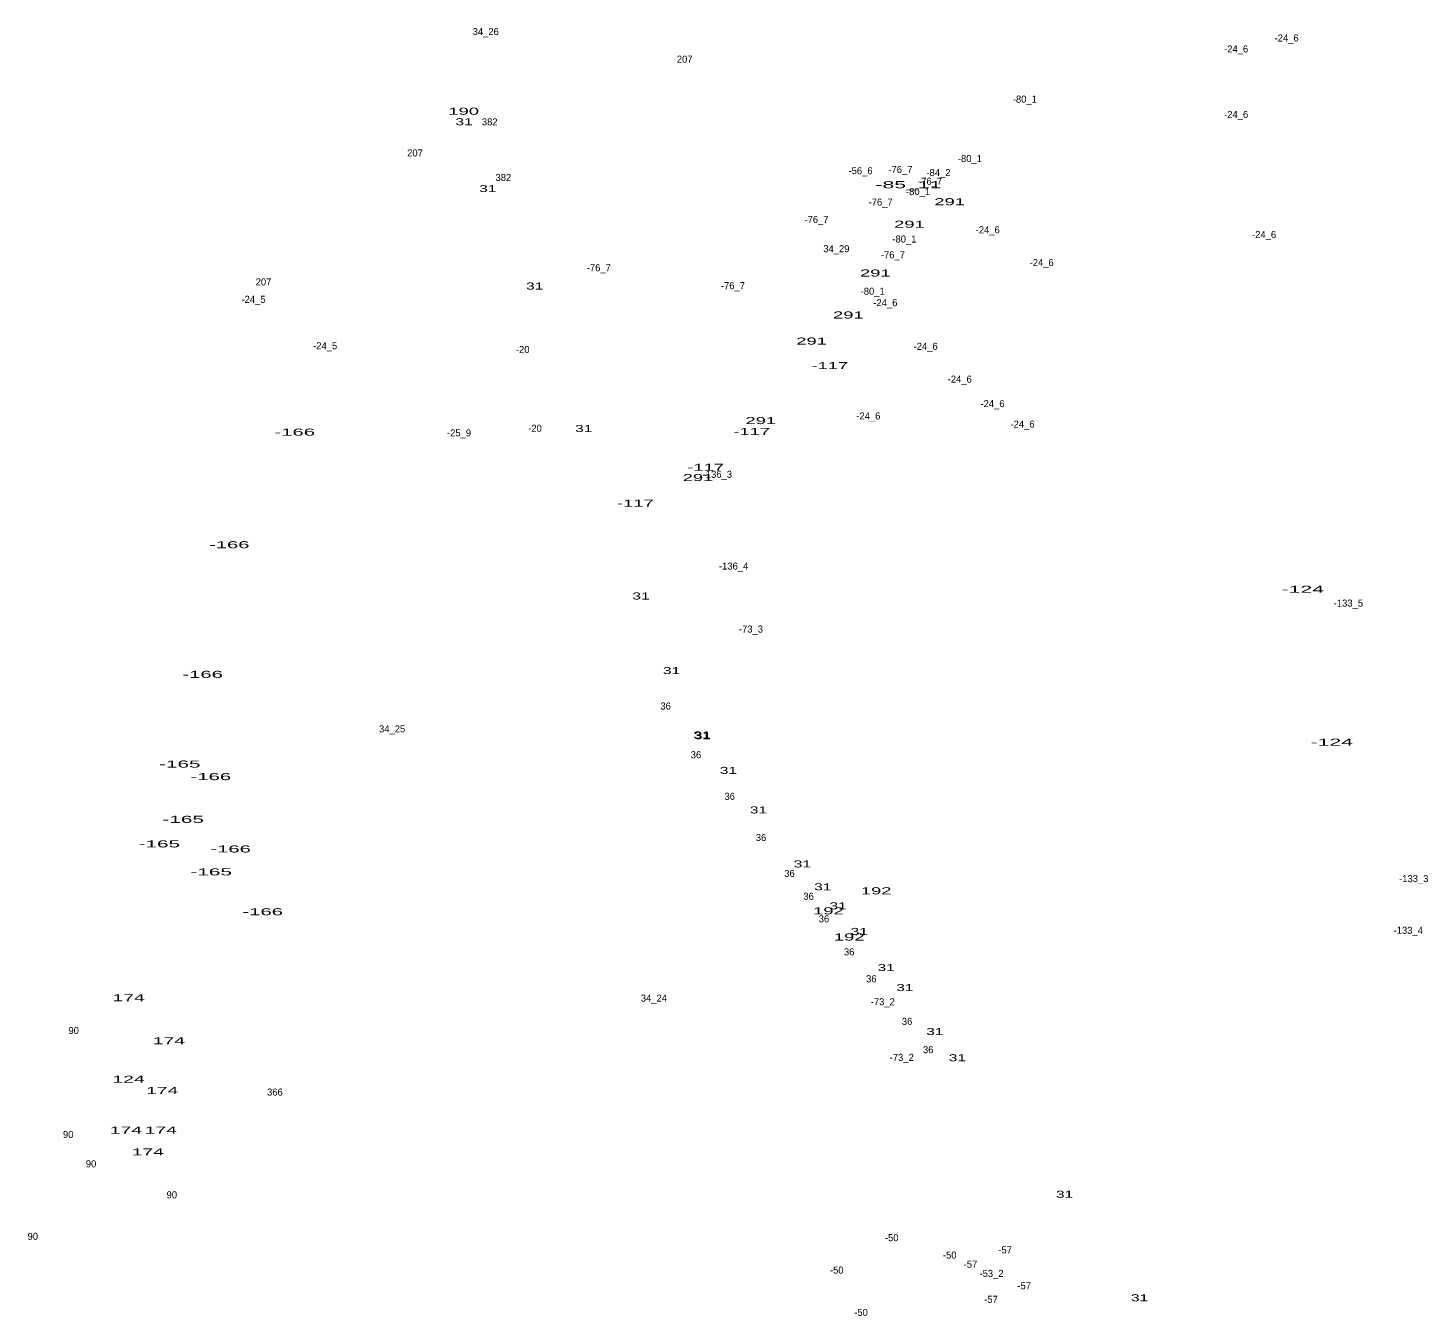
# Model space of a CAD drawing. Extents: x -662499 to -659675, y -1001682 to -998165.
# Drawn here: x -660470 to -659675, y -999900 to -999168 of the extents above; entities that cross this region are included whole.
import ezdxf
from ezdxf.enums import TextEntityAlignment as Align

# ---------------------------------------------------------------- set-up
doc = ezdxf.new("R2010")
doc.units = 0
doc.header["$LTSCALE"] = 1.6
doc.layers.add('24', color=7, linetype='Continuous')

msp = doc.modelspace()

# ---------------------------------------------------------------- texts
at = {"layer": '24'}
for s, p in [('34_26', (-660210.064, -999172.46)), ('-24_6', (-659754.992, -999176.09)), ('207', (-660097.017, -999188.1)), ('-24_6', (-659783.682, -999182.3)), ('-80_1', (-659903.74, -999210.82)), ('-24_6', (-659783.682, -999219.53)), ('382', (-660207.807, -999223.73)), ('207', (-660250.257, -999241.42)), ('-80_1', (-659934.95, -999244.56)), ('-56_6', (-659997.093, -999251.54)), ('-76_7', (-659974.438, -999250.82)), ('-84_2', (-659952.827, -999252.57)), ('382', (-660200.057, -999255.34)), ('-76_7', (-659957.578, -999257.51)), ('-80_1', (-659964.42, -999263.38)), ('-76_7', (-659985.688, -999269.34)), ('-76_7', (-660022.128, -999279.23)), ('-80_1', (-659972.17, -999290.33)), ('-24_6', (-659924.822, -999285.08)), ('-24_6', (-659767.792, -999287.8)), ('34_29', (-660010.834, -999295.85)), ('-76_7', (-659978.708, -999299.3)), ('-76_7', (-660145.818, -999306.67)), ('-24_6', (-659894.192, -999303.7)), ('207', (-660336.337, -999314.73)), ('-76_7', (-660069.628, -999316.85)), ('-80_1', (-659990.2, -999320.01)), ('-24_5', (-660342.027, -999324.62)), ('-24_6', (-659982.982, -999326.5)), ('-24_5', (-660301.317, -999351)), ('-20', (-660189.069, -999353.11)), ('-24_6', (-659960.102, -999351.32)), ('-24_6', (-659940.722, -999369.94)), ('-24_6', (-659922.112, -999383.9)), ('-24_6', (-659992.672, -999390.89)), ('-24_6', (-659905.042, -999395.54)), ('-25_9', (-660225.228, -999400.53)), ('-20', (-660182.089, -999397.91)), ('-136_3', (-660078.442, -999424.06)), ('-136_4', (-660069.226, -999476.21)), ('-133_5', (-659719.886, -999497.26)), ('-73_3', (-660059.378, -999512.01)), ('36', (-660107.853, -999555.75)), ('34_25', (-660263.26, -999568.75)), ('36', (-660090.623, -999583.45)), ('36', (-660071.453, -999607.08)), ('36', (-660053.643, -999630.52)), ('36', (-660037.453, -999650.91)), ('-133_3', (-659682.756, -999653.85)), ('36', (-660026.613, -999663.89)), ('36', (-660017.893, -999676.68)), ('-133_4', (-659685.86, -999683.23)), ('36', (-660003.563, -999695.47)), ('36', (-659990.983, -999710.77)), ('34_24', (-660114.514, -999721.75)), ('-73_2', (-659984.448, -999723.84)), ('36', (-659970.653, -999734.98)), ('90', (-660444.207, -999740.19)), ('36', (-659958.643, -999751.06)), ('-73_2', (-659973.688, -999755.45)), ('366', (-660329.858, -999775.17)), ('90', (-660447.307, -999799.27)), ('90', (-660434.327, -999815.93)), ('90', (-660388.437, -999833.55)), ('90', (-660467.437, -999857.18)), ('-50', (-659979.399, -999857.91)), ('-57', (-659914.961, -999864.86)), ('-50', (-659946.439, -999867.8)), ('-50', (-660010.609, -999876.34)), ('-57', (-659934.631, -999873.01)), ('-53_2', (-659922.672, -999878.23)), ('-57', (-659904.101, -999885.23)), ('-57', (-659923.001, -999892.98)), ('-50', (-659996.849, -999900.39))]:
    msp.add_text(s, height=4, dxfattribs=at).set_placement(p, align=Align.CENTER)
for s, width, p in [('190', 1.95, (-660222.619, -999217.72)), ('31', 1.65, (-660222.417, -999223.68)), ('-85_11', 2.25, (-659969.887, -999259.45)), ('31', 1.65, (-660208.857, -999261.65)), ('291', 1.95, (-659946.453, -999269.13)), ('291', 1.95, (-659969.323, -999281.93)), ('291', 1.95, (-659988.713, -999309.66)), ('31', 1.65, (-660182.257, -999317.05)), ('291', 1.95, (-660004.023, -999333.52)), ('291', 1.95, (-660024.903, -999348.33)), ('-117', 1.95, (-660014.541, -999362.28)), ('291', 1.95, (-660053.793, -999393.52)), ('-166', 2.15, (-660318.579, -999400.08)), ('31', 1.65, (-660154.367, -999398.01)), ('-117', 1.95, (-660058.931, -999399.7)), ('291', 1.95, (-660089.463, -999425.91)), ('-117', 1.95, (-660085.111, -999420.06)), ('-117', 1.95, (-660125.041, -999440.43)), ('-166', 2.15, (-660355.799, -999464.08)), ('-124', 2.25, (-659745.796, -999489.41)), ('31', 1.65, (-660121.837, -999493.23)), ('-166', 2.15, (-660370.919, -999537.76)), ('31', 1.65, (-660104.477, -999535.6)), ('31', 1.65, (-660087.237, -999572.21)), ('31', 1.65, (-660086.857, -999572.6)), ('-124', 2.25, (-659729.316, -999576.29)), ('-165', 2.2, (-660383.905, -999588.74)), ('31', 1.65, (-660072.137, -999592.35)), ('-166', 2.15, (-660366.269, -999595.88)), ('31', 1.65, (-660055.097, -999614.82)), ('-165', 2.2, (-660381.965, -999620.16)), ('-165', 2.2, (-660395.535, -999634.13)), ('-166', 2.15, (-660355.019, -999637)), ('-165', 2.2, (-660366.065, -999650.03)), ('31', 1.65, (-660030.177, -999645.52)), ('31', 1.65, (-660018.557, -999658.49)), ('192', 1.95, (-659988.233, -999660.76)), ('-166', 2.15, (-660336.799, -999672.68)), ('192', 1.95, (-660015.383, -999672.2)), ('31', 1.65, (-660009.847, -999669.34)), ('192', 1.95, (-660003.553, -999687.04)), ('31', 1.65, (-659997.837, -999683.87)), ('31', 1.65, (-659982.537, -999704.4)), ('174', 2.05, (-660412.938, -999721.54)), ('31', 1.65, (-659971.907, -999715.75)), ('31', 1.65, (-659954.867, -999740.74)), ('174', 2.05, (-660390.058, -999745.97)), ('31', 1.65, (-659942.087, -999755.66)), ('124', 2.05, (-660413.053, -999767.88)), ('174', 2.05, (-660393.938, -999774.29)), ('174', 2.05, (-660414.488, -999796.78)), ('174', 2.05, (-660394.708, -999796.78)), ('174', 2.05, (-660402.078, -999809.2)), ('31', 1.65, (-659881.157, -999833.25)), ('31', 1.65, (-659838.547, -999892.06))]:
    msp.add_text(s, height=4, dxfattribs=dict(at, width=width)).set_placement(p, align=Align.CENTER)

doc.saveas('drawing.dxf')
